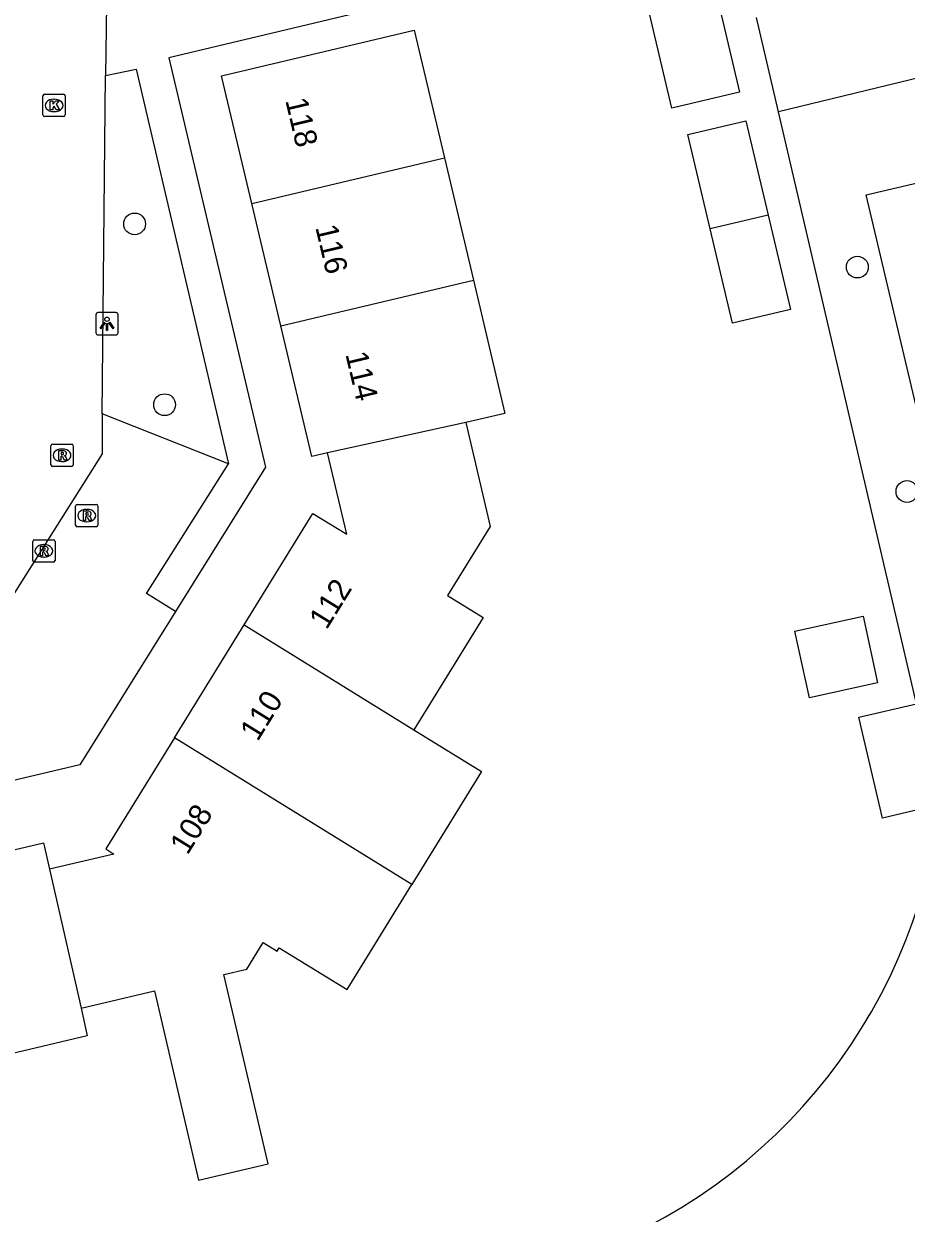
# Model space of a CAD drawing. Extents: x 158038 to 159242, y 380133 to 381214.
# Drawn here: x 158523.7 to 158563.3, y 381003.1 to 381056.5 of the extents above; entities that cross this region are included whole.
import ezdxf

# ---------------------------------------------------------------- set-up
doc = ezdxf.new("R2010")
doc.units = 0
for name, color, linetype in [('IMGEO_Boom', 7, 'Continuous'), ('IMGEO_Groenvoorziening', 7, 'Continuous'), ('IMGEO_Kolk', 7, 'Continuous'), ('IMGEO_Lichtpunt', 7, 'Continuous'), ('IMGEO_Pand', 7, 'Continuous'), ('IMGEO_Pand_nummerreeks', 7, 'Continuous'), ('IMGEO_Parkeervlak_open', 7, 'Continuous'), ('IMGEO_Rioolput', 7, 'Continuous'), ('IMGEO_Voetpad_open', 7, 'Continuous')]:
    doc.layers.add(name, color=color, linetype=linetype)

msp = doc.modelspace()

# ---------------------------------------------------------------- linework, layer by layer
at = {"layer": 'IMGEO_Boom'}
for centre in [(158528.659, 381047.507), (158561.068, 381045.574), (158530.003, 381039.4), (158563.292, 381035.506)]:
    msp.add_circle(centre, 0.489, dxfattribs=at)
at = {"layer": 'IMGEO_Groenvoorziening'}
for points in [[(158557.53, 381052.543), (158556.544, 381056.774)], [(158564.871, 381054.321), (158557.53, 381052.543)], [(158563.715, 381025.989), (158557.53, 381052.543)]]:
    msp.add_lwpolyline(points, dxfattribs=at)
msp.add_arc((158540.283, 381024.438), 24.68, 287.0029, 353.1004, dxfattribs=at)
at = {"layer": 'IMGEO_Kolk'}
for p, q in [((158524.548, 381052.398), (158524.548, 381053.25)), ((158524.623, 381053.324), (158525.475, 381053.324)), ((158525.549, 381053.25), (158525.549, 381052.398)), ((158525.036, 381053.104), (158525.061, 381053.104)), ((158525.475, 381052.324), (158524.623, 381052.324)), ((158525.059, 381052.544), (158525.034, 381052.544))]:
    msp.add_line(p, q, dxfattribs=at)
for points in [[(158524.548, 381052.398), (158524.548, 381053.25)], [(158524.623, 381053.324), (158525.475, 381053.324)], [(158525.549, 381053.25), (158525.549, 381052.398)], [(158524.869, 381053.024), (158524.992, 381053.024), (158524.992, 381052.873), (158525.122, 381053.024), (158525.286, 381053.024), (158525.14, 381052.873), (158525.293, 381052.624), (158525.141, 381052.624), (158525.056, 381052.788), (158524.992, 381052.721), (158524.992, 381052.624), (158524.869, 381052.624), (158524.869, 381053.024)], [(158525.475, 381052.324), (158524.623, 381052.324)]]:
    msp.add_lwpolyline(points, dxfattribs=at)
for centre, start, end in [((158524.625, 381053.248), 91.552, 178.448), ((158524.625, 381053.248), 91.552, 178.448), ((158525.473, 381053.248), 1.552, 88.448), ((158525.473, 381053.248), 1.552, 88.448), ((158524.625, 381052.4), 181.552, 268.448), ((158524.625, 381052.4), 181.552, 268.448), ((158525.473, 381052.4), 271.552, 358.448), ((158525.473, 381052.4), 271.552, 358.448)]:
    msp.add_arc(centre, 0.0765, start, end, dxfattribs=at)
for centre, major_axis, ratio, start_param, end_param in [((158525.035, 381052.824), (-0.387, 0.002), 0.722429, 4.712389, 7.853982), ((158525.06, 381052.824), (-0.39, 0.002), 0.717154, 1.570796, 4.712389)]:
    msp.add_ellipse(centre, major_axis=major_axis, ratio=ratio, start_param=start_param, end_param=end_param, dxfattribs=at)
at = {"layer": 'IMGEO_Lichtpunt'}
for p, q in [((158526.921, 381043.433), (158526.921, 381042.626)), ((158526.921, 381043.433), (158526.921, 381042.626)), ((158527.823, 381043.528), (158527.015, 381043.528)), ((158527.823, 381043.528), (158527.015, 381043.528)), ((158527.917, 381042.626), (158527.917, 381043.433)), ((158527.917, 381042.626), (158527.917, 381043.433)), ((158527.015, 381042.532), (158527.823, 381042.532)), ((158527.015, 381042.532), (158527.823, 381042.532))]:
    msp.add_line(p, q, dxfattribs=at)
for points in [[(158527.295, 381043.097), (158527.334, 381043.069), (158527.146, 381042.807), (158527.108, 381042.834), (158527.295, 381043.097)], [(158527.397, 381043.049), (158527.444, 381043.049), (158527.444, 381042.727), (158527.397, 381042.727), (158527.397, 381043.049)], [(158527.507, 381043.069), (158527.545, 381043.096), (158527.732, 381042.834), (158527.693, 381042.806), (158527.507, 381043.069)]]:
    msp.add_lwpolyline(points, dxfattribs=at)
msp.add_circle((158527.42, 381043.231), 0.0994, dxfattribs=at)
for centre, start, end in [((158527.015, 381043.433), 90, 180), ((158527.015, 381043.433), 90, 180), ((158527.823, 381043.433), 0, 90), ((158527.823, 381043.433), 0, 90), ((158527.015, 381042.626), 180, 270), ((158527.015, 381042.626), 180, 270), ((158527.823, 381042.626), 270, 0), ((158527.823, 381042.626), 270, 360)]:
    msp.add_arc(centre, 0.0946, start, end, dxfattribs=at)
at = {"layer": 'IMGEO_Pand'}
for points in [[(158554.079, 381060.657), (158555.79, 381053.425), (158552.751, 381052.706), (158551.04, 381059.938)], [(158533.915, 381048.431), (158532.561, 381054.153), (158541.198, 381056.196), (158542.553, 381050.47)], [(158554.467, 381047.29), (158553.466, 381051.52), (158556.073, 381052.137), (158557.074, 381047.905)], [(158533.915, 381048.431), (158542.553, 381050.47)], [(158542.553, 381050.47), (158543.851, 381044.979)], [(158535.214, 381042.94), (158533.915, 381048.431)], [(158557.074, 381047.905), (158558.075, 381043.675), (158555.468, 381043.058), (158554.467, 381047.29)], [(158557.074, 381047.905), (158554.467, 381047.29)], [(158535.214, 381042.94), (158543.851, 381044.979)], [(158543.851, 381044.979), (158545.263, 381039.012), (158543.507, 381038.597)], [(158537.309, 381037.247), (158536.6, 381037.079), (158535.214, 381042.94)], [(158543.507, 381038.597), (158537.309, 381037.247)], [(158543.507, 381038.597), (158544.608, 381033.942), (158542.693, 381030.84), (158544.291, 381029.853), (158541.183, 381024.818)], [(158533.567, 381029.52), (158536.657, 381034.525), (158538.174, 381033.588), (158537.309, 381037.247)], [(158561.322, 381029.914), (158561.978, 381026.919), (158558.919, 381026.249), (158558.262, 381029.243), (158561.322, 381029.914)], [(158530.442, 381024.458), (158533.567, 381029.52)], [(158533.567, 381029.52), (158541.183, 381024.818)], [(158564.784, 381021.473), (158562.203, 381020.862), (158561.134, 381025.379), (158563.715, 381025.989)], [(158530.442, 381024.458), (158527.365, 381019.474), (158527.733, 381019.247), (158524.846, 381018.564)], [(158541.093, 381017.882), (158530.442, 381024.458)], [(158541.183, 381024.818), (158544.218, 381022.944), (158541.093, 381017.882)], [(158518.732, 381018.368), (158524.566, 381019.748), (158524.846, 381018.564)], [(158524.846, 381018.564), (158526.263, 381012.332)], [(158526.263, 381012.332), (158529.547, 381013.109), (158531.525, 381004.621), (158534.647, 381005.349), (158532.666, 381013.847), (158533.689, 381014.089), (158534.422, 381015.277), (158535.052, 381014.888), (158535.147, 381015.042), (158538.183, 381013.168), (158541.093, 381017.882)], [(158526.263, 381012.332), (158526.537, 381011.096), (158520.773, 381009.733)]]:
    msp.add_lwpolyline(points, dxfattribs=at)
at = {"layer": 'IMGEO_Parkeervlak_open'}
for points in [[(158574.57, 381012.274), (158574.454, 381012.345), (158574.333, 381012.404), (158574.207, 381012.453), (158574.077, 381012.49), (158573.945, 381012.515), (158573.87, 381012.524), (158570.246, 381011.648), (158561.469, 381048.81), (158564.971, 381049.628), (158565.058, 381049.657), (158565.142, 381049.695), (158565.222, 381049.739), (158565.298, 381049.791), (158565.369, 381049.849), (158565.435, 381049.913), (158565.495, 381049.983), (158565.548, 381050.058), (158565.594, 381050.137)], [(158532.876, 381036.753), (158527.206, 381038.984)], [(158530.488, 381030.118), (158526.207, 381023.243), (158506.747, 381018.645)]]:
    msp.add_lwpolyline(points, dxfattribs=at)
at = {"layer": 'IMGEO_Rioolput'}
for p, q in [((158524.904, 381036.704), (158524.904, 381037.556)), ((158524.979, 381037.63), (158525.831, 381037.63)), ((158525.392, 381037.41), (158525.417, 381037.41)), ((158525.905, 381037.556), (158525.905, 381036.704)), ((158525.415, 381036.85), (158525.39, 381036.85)), ((158525.831, 381036.63), (158524.979, 381036.63)), ((158526.011, 381033.999), (158526.011, 381034.851)), ((158526.086, 381034.925), (158526.938, 381034.925)), ((158526.499, 381034.705), (158526.524, 381034.705)), ((158527.012, 381034.851), (158527.012, 381033.999)), ((158526.522, 381034.145), (158526.497, 381034.145)), ((158526.938, 381033.925), (158526.086, 381033.925)), ((158524.088, 381032.417), (158524.088, 381033.269)), ((158524.163, 381033.343), (158525.015, 381033.343)), ((158524.576, 381033.123), (158524.601, 381033.123)), ((158525.089, 381033.269), (158525.089, 381032.417)), ((158524.599, 381032.563), (158524.574, 381032.563)), ((158525.015, 381032.343), (158524.163, 381032.343))]:
    msp.add_line(p, q, dxfattribs=at)
for points in [[(158524.904, 381036.704), (158524.904, 381037.556)], [(158524.979, 381037.63), (158525.831, 381037.63)], [(158525.493, 381037.328), (158525.241, 381037.33), (158525.241, 381036.93)], [(158525.419, 381037.249), (158525.365, 381037.249), (158525.365, 381037.168)], [(158525.905, 381037.556), (158525.905, 381036.704)], [(158525.241, 381036.93), (158525.365, 381036.93), (158525.365, 381037.092), (158525.376, 381037.092)], [(158525.365, 381037.168), (158525.417, 381037.168)], [(158525.423, 381037.063), (158525.494, 381036.93), (158525.634, 381036.93), (158525.569, 381037.056)], [(158525.831, 381036.63), (158524.979, 381036.63)], [(158526.011, 381033.999), (158526.011, 381034.851)], [(158526.086, 381034.925), (158526.938, 381034.925)], [(158526.6, 381034.623), (158526.348, 381034.625), (158526.348, 381034.225)], [(158527.012, 381034.851), (158527.012, 381033.999)], [(158526.348, 381034.225), (158526.472, 381034.225), (158526.472, 381034.387), (158526.483, 381034.387)], [(158526.526, 381034.544), (158526.472, 381034.544), (158526.472, 381034.463)], [(158526.472, 381034.463), (158526.524, 381034.463)], [(158526.53, 381034.358), (158526.601, 381034.225), (158526.741, 381034.225), (158526.676, 381034.351)], [(158526.938, 381033.925), (158526.086, 381033.925)], [(158524.088, 381032.417), (158524.088, 381033.269)], [(158524.163, 381033.343), (158525.015, 381033.343)], [(158524.677, 381033.041), (158524.425, 381033.043), (158524.425, 381032.643)], [(158525.089, 381033.269), (158525.089, 381032.417)], [(158524.425, 381032.643), (158524.549, 381032.643), (158524.549, 381032.805), (158524.56, 381032.805)], [(158524.603, 381032.962), (158524.549, 381032.962), (158524.549, 381032.881)], [(158524.549, 381032.881), (158524.601, 381032.881)], [(158524.607, 381032.776), (158524.678, 381032.643), (158524.818, 381032.643), (158524.753, 381032.769)], [(158525.015, 381032.343), (158524.163, 381032.343)]]:
    msp.add_lwpolyline(points, dxfattribs=at)
for centre, radius, start, end in [((158524.981, 381037.554), 0.0765, 91.552, 178.448), ((158524.981, 381037.554), 0.0765, 91.552, 178.448), ((158525.425, 381037.153), 0.0964, 77.0061, 93.1865), ((158525.439, 381037.21), 0.0378, 276.6634, 79.6772), ((158525.492, 381037.218), 0.109, 350.3612, 89.416), ((158525.829, 381037.554), 0.0765, 1.552, 88.448), ((158525.829, 381037.554), 0.0765, 1.552, 88.448), ((158524.981, 381036.706), 0.0765, 181.552, 268.448), ((158524.981, 381036.706), 0.0765, 181.552, 268.448), ((158525.375, 381037.039), 0.0533, 26.0293, 88.6989), ((158525.401, 381037.357), 0.19, 274.7715, 282.9687), ((158525.49, 381037.218), 0.112, 277.5842, 350.9817), ((158525.474, 381037.003), 0.108, 29.5134, 73.7905), ((158525.829, 381036.706), 0.0765, 271.552, 358.448), ((158525.829, 381036.706), 0.0765, 271.552, 358.448), ((158526.088, 381034.849), 0.0765, 91.552, 178.448), ((158526.088, 381034.849), 0.0765, 91.552, 178.448), ((158526.599, 381034.513), 0.109, 350.3612, 89.416), ((158526.936, 381034.849), 0.0765, 1.552, 88.448), ((158526.936, 381034.849), 0.0765, 1.552, 88.448), ((158526.482, 381034.334), 0.0533, 26.0293, 88.6989), ((158526.508, 381034.652), 0.19, 274.7715, 282.9687), ((158526.532, 381034.448), 0.0964, 77.0061, 93.1865), ((158526.546, 381034.505), 0.0378, 276.6634, 79.6772), ((158526.597, 381034.513), 0.112, 277.5842, 350.9817), ((158526.581, 381034.298), 0.108, 29.5134, 73.7905), ((158526.088, 381034.001), 0.0765, 181.552, 268.448), ((158526.088, 381034.001), 0.0765, 181.552, 268.448), ((158526.936, 381034.001), 0.0765, 271.552, 358.448), ((158526.936, 381034.001), 0.0765, 271.552, 358.448), ((158524.165, 381033.267), 0.0765, 91.552, 178.448), ((158524.165, 381033.267), 0.0765, 91.552, 178.448), ((158524.609, 381032.866), 0.0964, 77.0061, 93.1865), ((158524.676, 381032.931), 0.109, 350.3612, 89.416), ((158525.013, 381033.267), 0.0765, 1.552, 88.448), ((158525.013, 381033.267), 0.0765, 1.552, 88.448), ((158524.559, 381032.752), 0.0533, 26.0293, 88.6989), ((158524.585, 381033.07), 0.19, 274.7715, 282.9687), ((158524.623, 381032.923), 0.0378, 276.6634, 79.6772), ((158524.674, 381032.931), 0.112, 277.5842, 350.9817), ((158524.658, 381032.716), 0.108, 29.5134, 73.7905), ((158524.165, 381032.419), 0.0765, 181.552, 268.448), ((158524.165, 381032.419), 0.0765, 181.552, 268.448), ((158525.013, 381032.419), 0.0765, 271.552, 358.448), ((158525.013, 381032.419), 0.0765, 271.552, 358.448)]:
    msp.add_arc(centre, radius, start, end, dxfattribs=at)
for centre, major_axis, ratio, start_param, end_param in [((158525.391, 381037.13), (-0.387, 0.002), 0.722429, 4.712389, 7.853982), ((158525.416, 381037.13), (-0.39, 0.002), 0.717154, 1.570796, 4.712389), ((158526.498, 381034.425), (-0.387, 0.002), 0.722429, 4.712389, 7.853982), ((158526.523, 381034.425), (-0.39, 0.002), 0.717154, 1.570796, 4.712389), ((158524.575, 381032.843), (-0.387, 0.002), 0.722429, 4.712389, 7.853982), ((158524.6, 381032.843), (-0.39, 0.002), 0.717154, 1.570796, 4.712389)]:
    msp.add_ellipse(centre, major_axis=major_axis, ratio=ratio, start_param=start_param, end_param=end_param, dxfattribs=at)
at = {"layer": 'IMGEO_Voetpad_open'}
for points in [[(158551.04, 381059.938), (158530.193, 381054.964), (158534.525, 381036.6), (158530.488, 381030.118)], [(158527.394, 381057.361), (158527.348, 381054.168)], [(158527.348, 381054.168), (158528.727, 381054.456), (158532.876, 381036.753)], [(158527.206, 381038.984), (158527.348, 381054.168)], [(158527.206, 381038.984), (158527.206, 381037.191), (158522.544, 381029.82), (158503.075, 381025.332), (158503.422, 381023.912)], [(158530.488, 381030.118), (158529.19, 381030.926), (158532.876, 381036.753)]]:
    msp.add_lwpolyline(points, dxfattribs=at)

# ---------------------------------------------------------------- texts
at = {"layer": 'IMGEO_Pand_nummerreeks'}
for s, rotation, p in [('118', 283.3091, (158535.411, 381053.049)), ('116', 283.3091, (158536.758, 381047.36)), ('114', 283.3091, (158538.104, 381041.668)), ('112', 58.3102, (158537.269, 381029.273)), ('110', 58.3102, (158534.175, 381024.261)), ('108', 58.3099, (158531.03, 381019.168))]:
    msp.add_text(s, height=1, rotation=rotation, dxfattribs=at).set_placement(p)

doc.saveas('drawing.dxf')
